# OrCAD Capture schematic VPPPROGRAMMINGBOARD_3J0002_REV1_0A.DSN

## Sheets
1 Pg02: Voltage Regulator: size C; title: Vpp Programming Board; rev: 1.0A; company: Texas Instruments; note: vppprogrammingboard_3J0002.dsn; note: Catalog Processors BU; note: Final
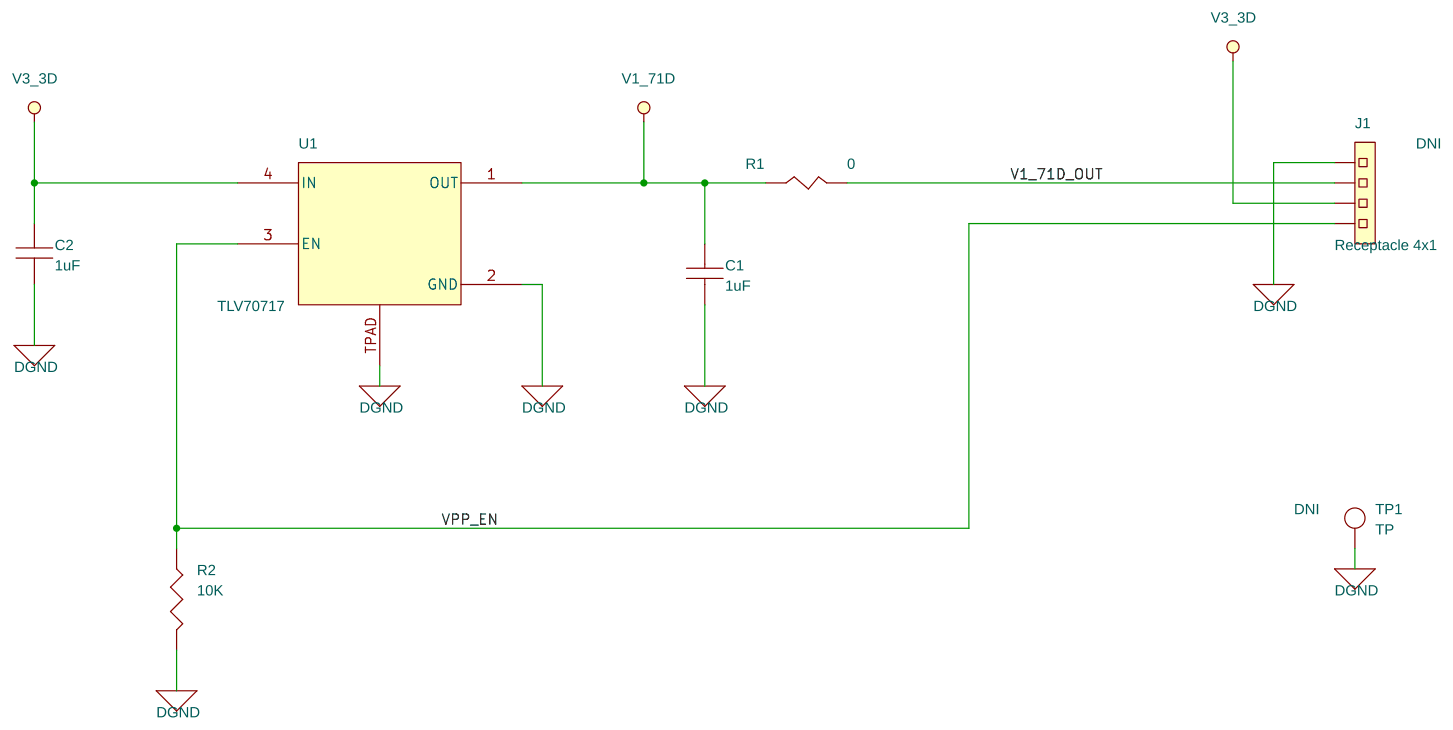
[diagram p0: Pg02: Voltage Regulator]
2 Pg01: Title
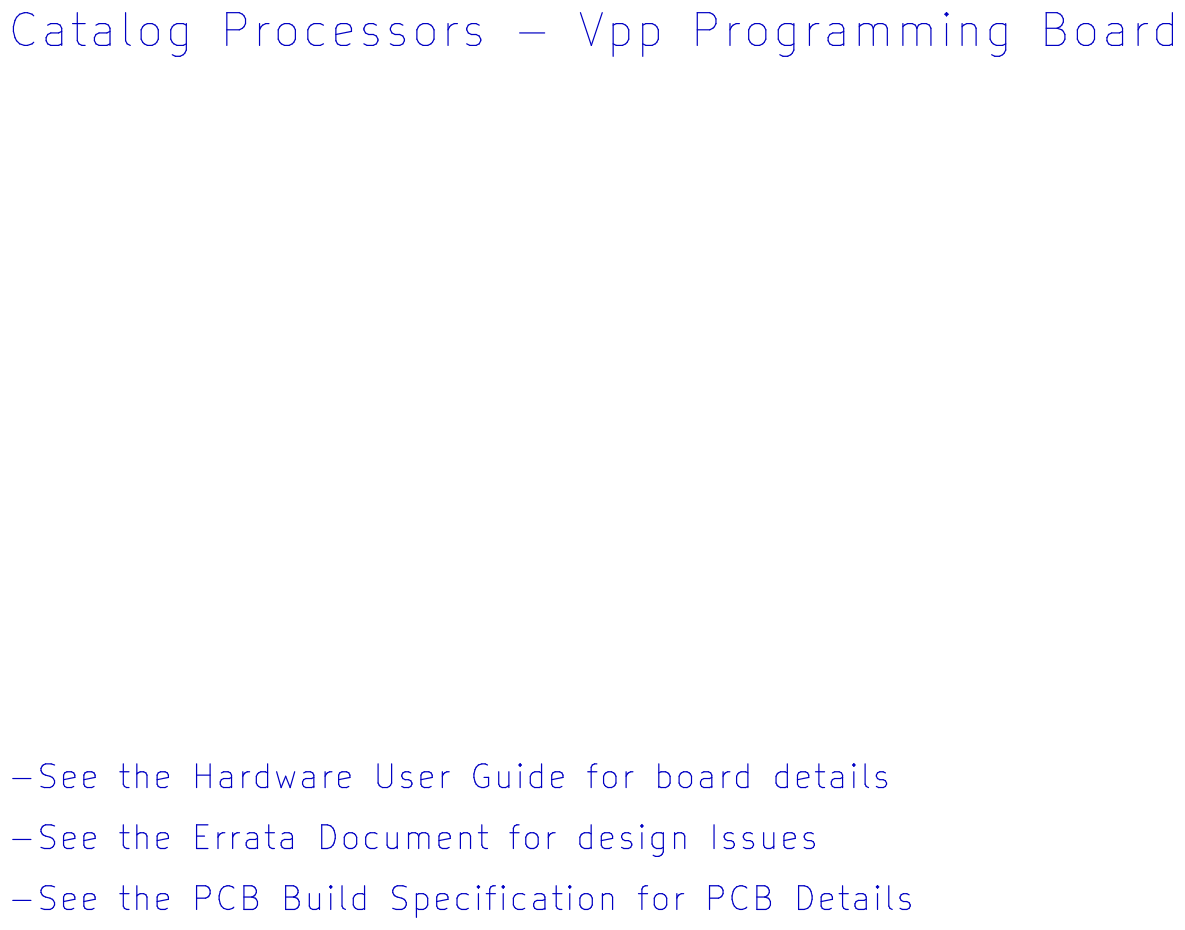
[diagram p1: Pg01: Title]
3 Pg03: Hardware Schematics
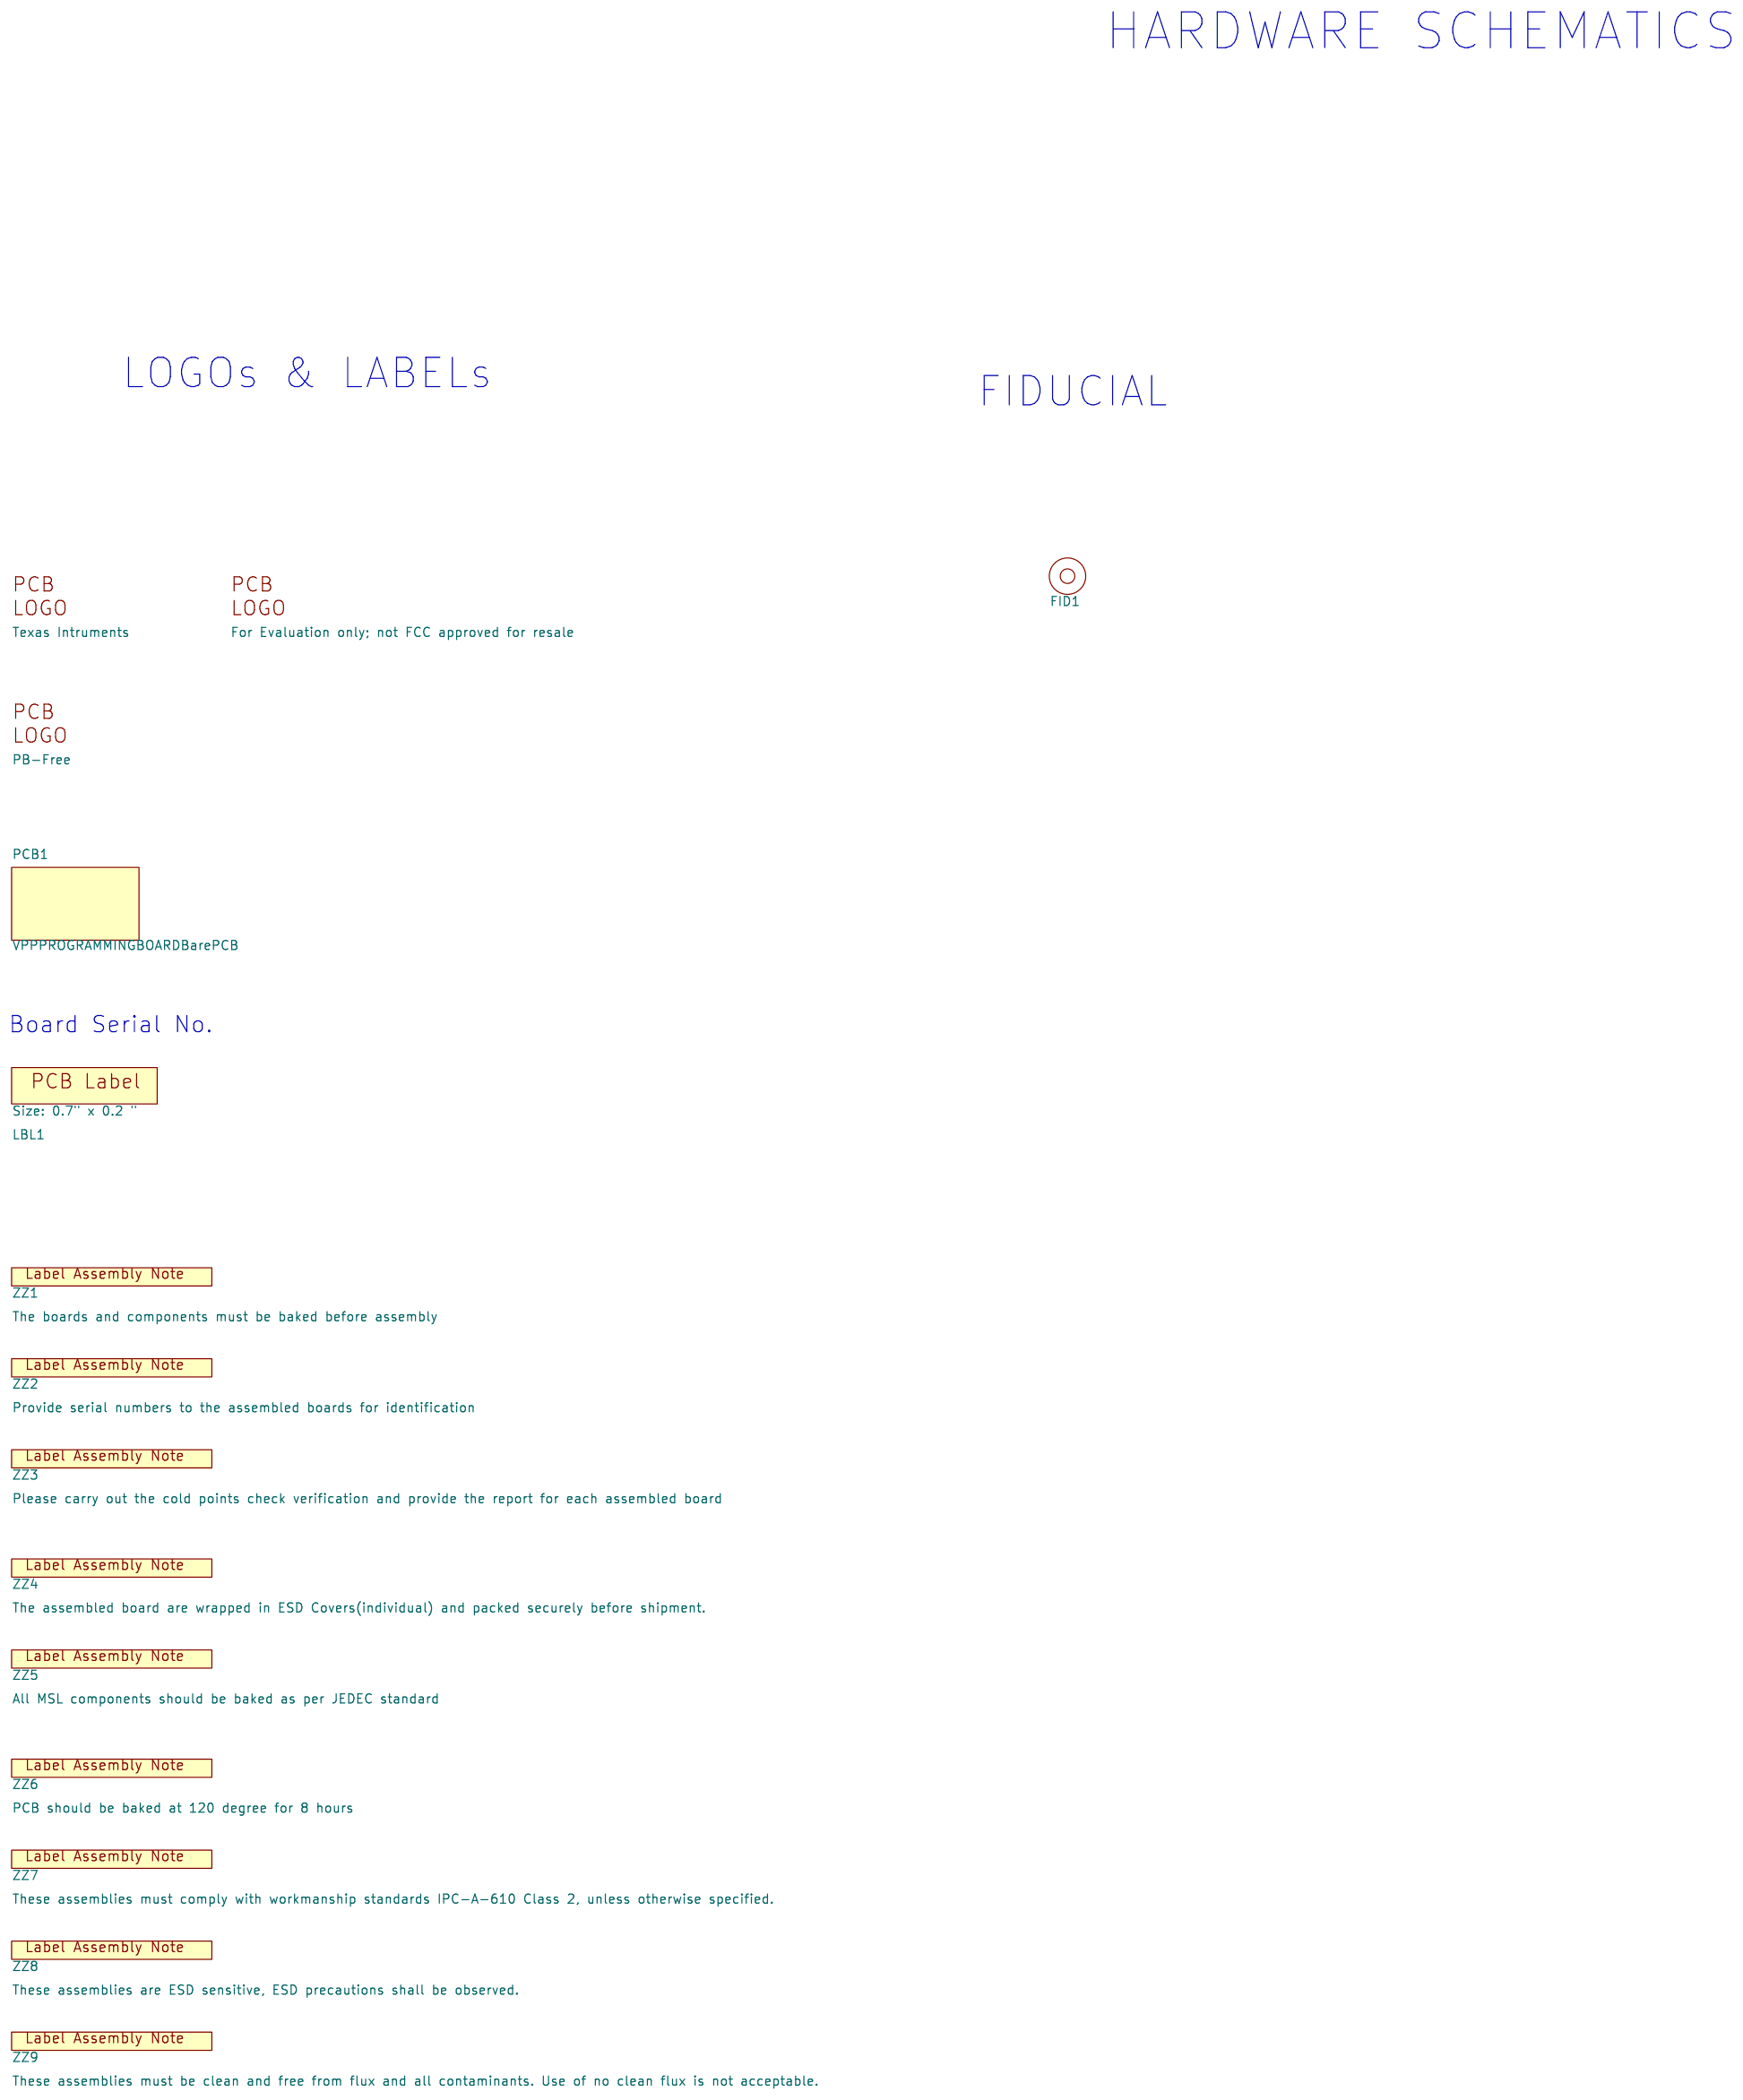
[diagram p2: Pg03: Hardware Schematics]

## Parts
sheet Pg02: Voltage Regulator
C1  1uF  [SM-7351-CAP-0603]
C2  1uF  [SM-7351-CAP-0603]
J1  Receptacle 4x1  [HDR4X1RA-108M]
R1  0  [SM-7351-RES-0603]
R2  10K  [SM-7351-RES-0402]
TP1  TP  [TH_TP_5002]
U1  TLV70717  [X2SON1X1-4-16M]
sheet Pg03: Hardware Schematics
FID1  Fiducial  [Fiducial10-20]
LBL1  Size: 0.7" x 0.2 "  [Label_650x200]
LOGO1  Texas Intruments  [TI_Stacked_Overlay_Small]
LOGO2  PB-Free  [TI_Stacked_Overlay_Small]
LOGO4  For Evaluation only; not FCC approved for resale  [FCC_disclaimer]
PCB1  VPPPROGRAMMINGBOARDBarePCB  [DNP]
ZZ1  The boards and components must be baked before assembly  [AssemblyNoteLabel]
ZZ2  Provide serial numbers to the assembled boards for identification  [AssemblyNoteLabel]
ZZ3  Please carry out the cold points check verification and provide the report for each assembled board  [AssemblyNoteLabel]
ZZ4  The assembled board are wrapped in ESD Covers(individual) and packed securely before shipment.  [AssemblyNoteLabel]
ZZ5  All MSL components should be baked as per JEDEC standard  [AssemblyNoteLabel]
ZZ6  PCB should be baked at 120 degree for 8 hours  [AssemblyNoteLabel]
ZZ7  These assemblies must comply with workmanship standards IPC-A-610 Class 2, unless otherwise specified.  [AssemblyNoteLabel]
ZZ8  These assemblies are ESD sensitive, ESD precautions shall be observed.  [AssemblyNoteLabel]
ZZ9  These assemblies must be clean and free from flux and all contaminants. Use of no clean flux is not acceptable.  [AssemblyNoteLabel]

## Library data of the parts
C1 C2 = 1C_1uFCapacitor50V10%0603
J1 = 2H_Header_4x1_female: Loading: DNI
R1 = 1R_ZeroOhmResistor1_16W0603
R2 = 1R_10KOhmResistor1_16W0402
TP1 = 2H_TestPointThroughHole: Loading: DNI
U1 = 1A_TLV70717
FID1 = Fiducial
LBL1 = THT-14-423-10: Serail Number Label
LOGO1 LOGO2 = TI_Logo
LOGO4 = FCC_disclaimer
PCB1 = 3K_2MpCameraBoardBarePCBv1_3: DescriptiveText: VPPPROGRAMMINGBOARD Rev1_0A Bare PCB; MfrNum: 3J0002; Mistral Part No: M160016090001; PartName: VPPPROGRAMMINGBOARD Rev1_0A Bare PCB; TIIntPartnumber: 3J0002
ZZ1-ZZ9 = AssemblyNoteLabel_0

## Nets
DGND: C1.2 C2.2 J1.1 R2.1(P1) TP1.1 U1.2(GND) U1.TPAD
V1_71D: C1.1 R1.2(P2) U1.1(OUT)
V1_71D_OUT: J1.2 R1.1(P1)
V3_3D: C2.1 J1.3 U1.4(IN)
VPP_EN: J1.4 R2.2(P2) U1.3(EN)

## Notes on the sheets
sheet 2
- Catalog Processors - Vpp Programming Board
- -See the Hardware User Guide for board details
- -See the Errata Document for design Issues
- -See the PCB Build Specification for PCB Details
sheet 3
- HARDWARE SCHEMATICS
- LOGOs & LABELs
- FIDUCIAL
- Board Serial No.
